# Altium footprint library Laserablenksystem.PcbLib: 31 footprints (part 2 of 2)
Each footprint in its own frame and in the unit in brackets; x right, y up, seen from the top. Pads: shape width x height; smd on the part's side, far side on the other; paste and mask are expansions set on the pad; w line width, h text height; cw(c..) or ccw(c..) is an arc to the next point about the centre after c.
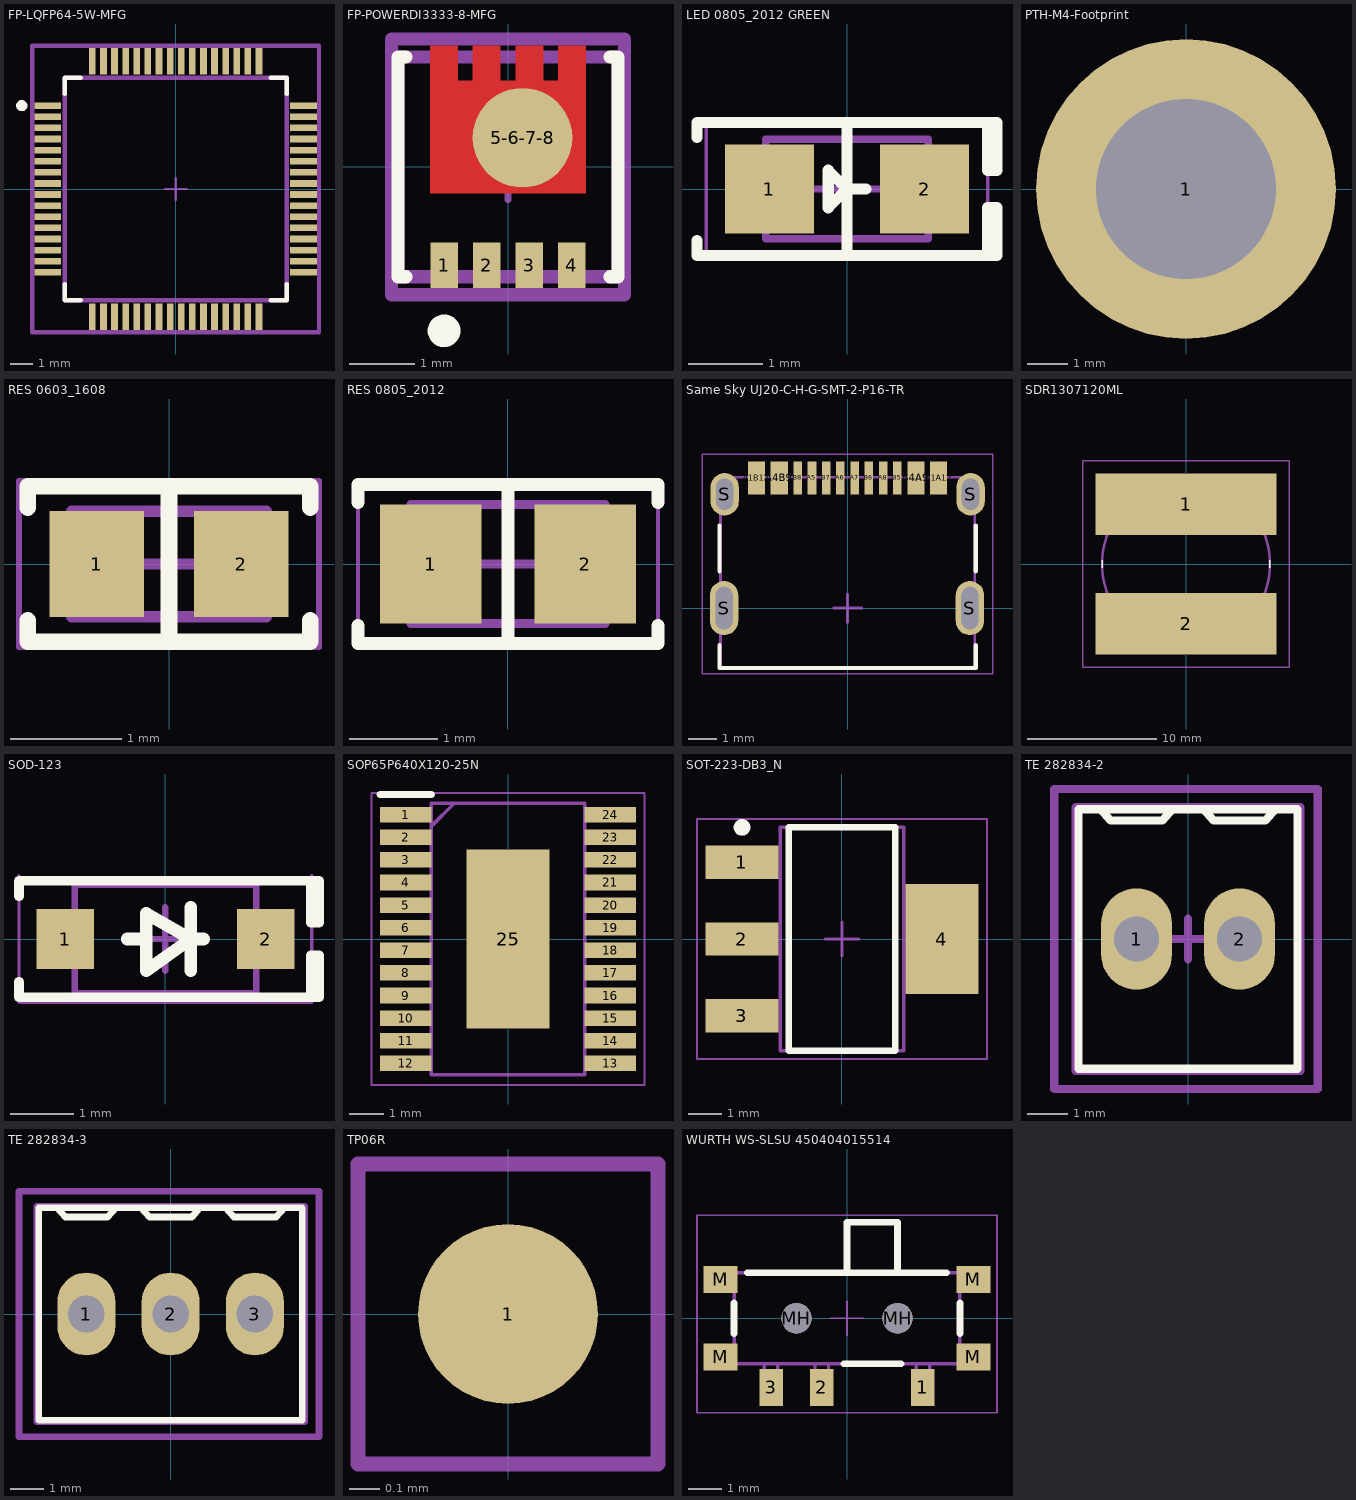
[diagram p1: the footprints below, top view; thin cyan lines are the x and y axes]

## FP-LQFP64-5W-MFG [mm]
pads (64):
  rect 1.2x0.3 smd paste+0 mask+0: 1(-5.75,3.75) 2(-5.75,3.25) 3(-5.75,2.75) 4(-5.75,2.25) 5(-5.75,1.75) 6(-5.75,1.25) 7(-5.75,0.75) 8(-5.75,0.25) 9(-5.75,-0.25) 10(-5.75,-0.75) 11(-5.75,-1.25) 12(-5.75,-1.75) 13(-5.75,-2.25) 14(-5.75,-2.75) 15(-5.75,-3.25) 16(-5.75,-3.75) 33(5.75,-3.75) 34(5.75,-3.25) 35(5.75,-2.75) 36(5.75,-2.25) 37(5.75,-1.75) 38(5.75,-1.25) 39(5.75,-0.75) 40(5.75,-0.25) 41(5.75,0.25) 42(5.75,0.75) 43(5.75,1.25) 44(5.75,1.75) 45(5.75,2.25) 46(5.75,2.75) 47(5.75,3.25) 48(5.75,3.75)
  rect 0.3x1.2 smd paste+0 mask+0: 17(-3.75,-5.75) 18(-3.25,-5.75) 19(-2.75,-5.75) 20(-2.25,-5.75) 21(-1.75,-5.75) 22(-1.25,-5.75) 23(-0.75,-5.75) 24(-0.25,-5.75) 25(0.25,-5.75) 26(0.75,-5.75) 27(1.25,-5.75) 28(1.75,-5.75) 29(2.25,-5.75) 30(2.75,-5.75) 31(3.25,-5.75) 32(3.75,-5.75) 49(3.75,5.75) 50(3.25,5.75) 51(2.75,5.75) 52(2.25,5.75) 53(1.75,5.75) 54(1.25,5.75) 55(0.75,5.75) 56(0.25,5.75) 57(-0.25,5.75) 58(-0.75,5.75) 59(-1.25,5.75) 60(-1.75,5.75) 61(-2.25,5.75) 62(-2.75,5.75) 63(-3.25,5.75) 64(-3.75,5.75)
Top Overlay:
  circle w0.25: c-6.925,3.75 r0.125
  lines w0.2: -5,-4.275 -5,-5 -4.275,-5 ; -5,4.275 -5,5 -4.275,5 ; 4.275,-5 5,-5 5,-4.275 ; 4.275,5 5,5 5,4.275
Top 3D Body:
  lines w0.2: -5,-5 5,-5 5,5 -5,5 -5,-5
Top Courtyard:
  lines w0.2: -6.45,-6.45 6.45,-6.45 6.45,6.45 -6.45,6.45 -6.45,-6.45
Top Assembly:
  lines w0.2: -6.45,-6.45 6.45,-6.45 6.45,6.45 -6.45,6.45 -6.45,-6.45
  text ".Designator" at 0,0.188 h1
Top Component Center:
  lines w0.1: -0.5,0 0.5,0 ; 0,-0.5 0,0.5
3D body "IC_STMicroelectronics_STM32L496RGT3_eec.STEP": height 0.25, standoff 0, extent -6.45,-6.45 6.45,6.45

## FP-POWERDI3333-8-MFG [mm]
pads (5):
  rect 0.42x0.7 smd paste+0 mask+0: 1(-0.975,-1.5) 2(-0.325,-1.5) 3(0.325,-1.5) 4(0.975,-1.5)
  round 1.519 smd paste+0 mask+0: 5-6-7-8(0.221,0.444)
Top Layer:
  region: -1.185,1.85 -0.765,1.85 -0.765,1.31 -0.535,1.31 -0.535,1.85 -0.115,1.85 -0.115,1.31 0.115,1.31 0.115,1.85 0.535,1.85 0.535,1.31 0.765,1.31 0.765,1.85 1.185,1.85 1.185,-0.4 -1.185,-0.4
Top Overlay:
  circle w0.25: c-0.975,-2.5 r0.125
  lines w0.2: -1.56,-1.675 -1.675,-1.675 -1.675,1.675 -1.56,1.675 ; 1.56,-1.675 1.675,-1.675 1.675,1.675 1.56,1.675
Top 3D Body:
  lines w0.2: -1.675,-1.675 -1.675,1.675 1.675,1.675 1.675,-1.675 -1.675,-1.675
Top Courtyard:
  lines w0.2: -1.775,-1.95 -1.775,1.95 1.775,1.95 1.775,-1.95 -1.775,-1.95
Top Assembly:
  lines w0.2: -1.775,-1.95 -1.775,1.95 1.775,1.95 1.775,-1.95 -1.775,-1.95
  text ".Designator" at 0,-0.001 h1
Top Component Center:
  lines w0.1: -0.5,0 0.5,0 ; 0,-0.5 0,0.5
3D body "Trans_Diodes_DMT6007LFGQ-13_eec.STEP": height 0.25, standoff 0, extent -1.775,-1.95 1.775,1.95

## LED 0805_2012 GREEN [mm] "Chip Diode, 2-Leads, Body 2.00x1.25mm, IPC Medium Density"
height 0.7
pads (2):
  rect 1.2x1.2 smd: 1(-1.05,0) 2(1.05,0)
Top Overlay:
  lines w0.15: -2.032,-0.7 -2.032,-0.9 1.905,-0.9 ; -2.032,0.7 -2.032,0.9 1.905,0.9 ; 0,-0.9 0,0.9 ; 0.254,0 0,0 ; 0,0 -0.254,-0.254 -0.254,0.254 0,0 ; 1.905,-0.9 2.032,-0.9 2.032,-0.254 1.905,-0.254 1.905,-0.9 ; 1.905,0.9 2.032,0.9 2.032,0.254 1.905,0.254 1.905,0.9
Mechanical 13:
  lines w0.1: -1.1,-0.675 -1.1,0.675 1.1,0.675 1.1,-0.675 -1.1,-0.675
Mechanical 15:
  lines w0.05: -1.905,-0.95 -1.905,0.95 1.905,0.95 1.905,-0.95 -1.905,-0.95
  lines w0.1: -0.5,0 0.5,0 ; 0,-0.5 0,0.5
3D body "LED 0805 Lens GREEN.STEP": height 0.9, standoff 0.3, extent -0.65,-0.625 0.65,0.625
3D body "LED 0805 Base GREEN.STEP": height 0.4, standoff 0, extent -1,-0.625 1,0.625

## PTH-M4-Footprint [mm]
pads (1):
  round 7.5 hole 4.5: 1(0,0)

## RES 0603_1608 [mm] "Chip Resistor, 2-Leads, Body 1.60x0.80mm, IPC Medium Density"
height 0.45
pads (2):
  rect 0.85x0.95 smd: 1(-0.65,0) 2(0.65,0)
Top Overlay:
  lines w0.15: -1.27,-0.508 -1.27,-0.7 1.27,-0.7 1.27,-0.508 ; -1.27,0.508 -1.27,0.7 1.27,0.7 1.27,0.508 ; 0,-0.7 0,0.7
Mechanical 13:
  lines w0.1: -0.875,-0.475 -0.875,0.475 0.875,0.475 0.875,-0.475 -0.875,-0.475
Mechanical 15:
  lines w0.05: -1.35,-0.75 -1.35,0.75 1.35,0.75 1.35,-0.75 -1.35,-0.75
  lines w0.1: -0.475,0 0.475,0 ; 0,-0.475 0,0.475
3D body "0603 resistor.STEP": height 0.45, standoff 0, extent -0.8,-0.4 0.8,0.4

## RES 0805_2012 [mm] "Chip Resistor, 2-Leads, Body 2.00x1.25mm, IPC Medium Density"
height 0.7
pads (2):
  rect 1.15x1.35 smd: 1(-0.875,0) 2(0.875,0)
Top Overlay:
  lines w0.15: -1.7,-0.7 -1.7,-0.9 1.7,-0.9 1.7,-0.7 ; -1.7,0.7 -1.7,0.9 1.7,0.9 1.7,0.7 ; 0,-0.9 0,0.9
Mechanical 13:
  lines w0.1: -1.1,-0.675 -1.1,0.675 1.1,0.675 1.1,-0.675 -1.1,-0.675
Mechanical 15:
  lines w0.05: -1.7,-0.95 -1.7,0.95 1.7,0.95 1.7,-0.95 -1.7,-0.95
  lines w0.1: -0.5,0 0.5,0 ; 0,-0.5 0,0.5
3D body "0805 resistor.STEP": height 0.6, standoff 0, extent -1,-0.625 1,0.625

## Same Sky UJ20-C-H-G-SMT-2-P16-TR [mm] "Type C, USB 2.0, 480 Mbps, 48 Vdc, 5 A, Horizontal, Surface Mount Anchor Pins Mounting Style, Surface Mount Contact Pin Type, Gold Plated 3 µin, 16 Pins, USB Receptacle"
height 3.16
pads (16):
  rect 0.6x1.15 smd: A1B12(-3.2,4.575) A4B9(-2.4,4.575) B1A12(3.2,4.575) B4A9(2.4,4.575)
  rect 0.3x1.15 smd: A5(-1.25,4.575) A6(-0.25,4.575) A7(0.25,4.575) A8(1.25,4.575) B5(1.75,4.575) B6(0.75,4.575) B7(-0.75,4.575) B8(-1.75,4.575)
  oval 1x1.9 hole 0.6 slot 1.5 at 90 deg: S(-4.34,0) S(4.3,0)
  oval 1x1.5 hole 0.6 slot 1.1 at 90 deg: S(-4.32,4) S(4.32,4)
Top Overlay:
  lines w0.15: -4.5,-1.3 -4.5,-2.1 4.5,-2.1 4.5,-1.3 ; -4.5,1.3 -4.5,2.9 ; 4.5,1.3 4.5,2.9
Mechanical 13:
  lines w0.1: -4.47,-2.1 -4.47,4.6 4.47,4.6 4.47,-2.1 -4.47,-2.1
Mechanical 15:
  lines w0.05: -5.1,-2.3 -5.1,5.4 5.1,5.4 5.1,-2.3 -5.1,-2.3
  lines w0.1: -0.5,0 0,0 ; 0,-0.5 0,0 ; 0,0.5 0,0 ; 0.5,0 0,0
3D body "Same Sky UJ20-C-H-G-SMT-2-P16-TR.step": height 3.26, standoff -0.51, extent -4.47,-2.1 4.47,4.65

## SDR1307120ML [mm]
pads (2):
  rect 14x4.75 smd: 1(0,4.625) 2(0,-4.625)
Top Overlay:
  lines w0.1: -6.5,-0.3 -6.5,0.3 ; 6.5,-0.3 6.5,0.3
Mechanical 13:
  lines w0.2: -6.5,0 ccw(c0,0) 6.5,0 ccw(c0,0) -6.5,0
Mechanical 15:
  lines w0.1: -8,-8 -8,8 8,8 8,-8 -8,-8
3D body "SDR1307-120ML.stp": height 7, standoff 0, extent -6.5,-6.5 6.5,6.5

## SOD-123 [mm] "SOD, 2-Leads, Body 1.55x3.70mm, IPC Medium Density"
height 1.35
pads (2):
  rect 0.9x0.95 smd: 1(-1.575,0) 2(1.575,0)
Top Overlay:
  lines w0.15: -2.3,-0.675 -2.3,-0.916 2.286,-0.916 ; -2.3,0.675 -2.3,0.916 2.286,0.916 ; 2.286,-0.916 2.286,-0.254 2.413,-0.254 2.413,-0.916 2.286,-0.916 ; 2.286,0.916 2.413,0.916 2.413,0.254 2.286,0.254 2.286,0.916
  lines w0.2: -0.6,0 -0.3,0 ; 0.4,-0.5 0.4,0.5 ; 0.6,0 0.4,0 ; 0.4,0 -0.3,-0.5 -0.3,0.4 0.4,0
Mechanical 13:
  lines w0.1: -1.425,-0.85 1.425,-0.85 1.425,0.85 -1.425,0.85 -1.425,-0.85
Mechanical 15:
  lines w0.05: -2.3,0.9 2.3,0.9 ; -2.3,1 -2.3,-1 2.3,-1 2.3,1
  lines w0.1: -0.5,0 0.5,0 ; 0,-0.5 0,0.5
3D body "SOD-123.STEP": height 1.35, standoff 0, extent -1.864,-0.775 1.864,0.775

## SOP65P640X120-25N [mm]
pads (25):
  rect 1.475x0.45 smd: 1(-2.938,3.575) 2(-2.938,2.925) 3(-2.938,2.275) 4(-2.938,1.625) 5(-2.938,0.975) 6(-2.938,0.325) 7(-2.938,-0.325) 8(-2.938,-0.975) 9(-2.938,-1.625) 10(-2.938,-2.275) 11(-2.938,-2.925) 12(-2.938,-3.575) 13(2.938,-3.575) 14(2.938,-2.925) 15(2.938,-2.275) 16(2.938,-1.625) 17(2.938,-0.975) 18(2.938,-0.325) 19(2.938,0.325) 20(2.938,0.975) 21(2.938,1.625) 22(2.938,2.275) 23(2.938,2.925) 24(2.938,3.575)
  rect 2.4x5.16 smd: 25(0,0)
Top Overlay:
  lines w0.2: -3.675,4.15 -2.2,4.15
Mechanical 13:
  lines w0.1: -2.2,3.25 -1.55,3.9 ; -2.2,-3.9 -2.2,3.9 2.2,3.9 2.2,-3.9 -2.2,-3.9
Mechanical 15:
  lines w0.05: -3.925,-4.2 -3.925,4.2 3.925,4.2 3.925,-4.2 -3.925,-4.2
3D body "DRV10975ZPWPR.stp": height 1, standoff 0, extent -3.21,-3.9 3.21,3.9

## SOT-223-DB3_N [mm] "SOT223, 4-Leads, Body 6.5x3.5mm, Pitch 2.3mm, Lead Span 7mm, IPC Medium Density"
height 1.8
pads (4):
  rect 2.2x1 smd: 1(-3,2.3) 2(-3,0) 3(-3,-2.3)
  rect 2.2x3.3 smd: 4(3,0)
Top Overlay:
  circle w0.25: c-3,3.35 r0.125
  lines w0.2: -1.6,-3.35 1.6,-3.35 1.6,3.35 -1.6,3.35 -1.6,-3.35
Mechanical 13:
  lines w0.1: -1.85,-3.35 1.85,-3.35 1.85,3.35 -1.85,3.35 -1.85,-3.35
Mechanical 15:
  lines w0.05: -4.35,-3.6 4.35,-3.6 4.35,3.6 -4.35,3.6 -4.35,-3.6
  lines w0.1: -0.5,0 0.5,0 ; 0,-0.5 0,0.5
3D body: height 1.8, standoff 0.02, extent -1.85,-3.35 1.85,3.35

## TE 282834-2 [mm]
height 10
pads (2):
  oval 1.75x2.5 hole 1.1: 1(-1.27,0) 2(1.27,0)
Top Overlay:
  lines w0.2: -2.159,3.2 -1.905,2.921 -0.635,2.921 -0.381,3.2 ; 0.381,3.2 0.635,2.921 1.905,2.921 2.159,3.2 ; -2.7,-3.2 -2.6,-3.2 2.7,-3.2 2.7,3.2 -2.7,3.2 -2.7,-3.2
Mechanical 13:
  lines w0.2: -2.77,-3.25 -2.77,3.25 2.77,3.25 2.77,-3.25 -2.77,-3.25
Mechanical 15:
  lines w0.2: -0.5,0 0.5,0 ; 0,-0.5 0,0.5 ; -3.3,-3.7 3.2,-3.7 3.2,-2.9 3.2,3.7 -3.3,3.7 -3.3,-3.3 -3.3,-3.7
3D body "TE Term Block 2port 282834-2-c-3d.STEP": height 10, standoff -3.4, extent -2.77,-3.25 2.77,3.25

## TE 282834-3 [mm]
height 10
pads (3):
  oval 1.75x2.5 hole 1.1: 1(-2.54,0) 2(0,0) 3(2.54,0)
Top Overlay:
  lines w0.2: -3.429,3.2 -3.175,2.921 -1.905,2.921 -1.651,3.2 ; -0.889,3.2 -0.635,2.921 0.635,2.921 0.889,3.2 ; 1.651,3.2 1.905,2.921 3.175,2.921 3.429,3.2 ; -3.97,-3.2 -3.87,-3.2 3.97,-3.2 3.97,3.2 -3.97,3.2 -3.97,-3.2
Mechanical 13:
  lines w0.2: -4.04,-3.25 -4.04,3.25 4.04,3.25 4.04,-3.25 -4.04,-3.25
Mechanical 15:
  lines w0.2: -0.5,0 0.5,0 ; 0,-0.5 0,0.5 ; -4.57,-3.7 4.47,-3.7 4.47,-2.9 4.47,3.7 -4.57,3.7 -4.57,-3.3 -4.57,-3.7
3D body "TE Term Block 3port 282834-3-c-3d.STEP": height 10, standoff -3.4, extent -4.04,-3.25 4.04,3.25

## TP06R [mm] "Testpoint, round, d=0.6mm"
pads (1):
  round 0.6 smd paste-1: 1(0,0)
Top Assembly:
  lines w0.05: -0.5,-0.5 0.5,-0.5 0.5,0.5 -0.5,0.5 -0.5,-0.5
Top Designator:
  text ".Designator" at -1.27,0.254 h0.6

## WURTH WS-SLSU 450404015514 [mm] "Right angle Slide Switch"
height 1.4
pads (9):
  rect 0.7x1.1 smd: 1(2.25,-2.05) 2(-0.75,-2.05) 3(-2.25,-2.05)
  rect 1x0.8 smd: M(-3.75,-1.15) M(-3.75,1.15) M(3.75,-1.15) M(3.75,1.15)
  round 0.9 hole 0.9 unplated: MH(-1.5,0) MH(1.5,0)
Top Overlay:
  lines w0.2: -3.35,-0.45 -3.35,0.45 ; -2.95,1.35 2.95,1.35 ; -0.1,-1.35 1.6,-1.35 ; 0,1.35 0,2.85 1.5,2.85 1.5,1.35 ; 3.35,-0.45 3.35,0.45
Top Courtyard:
  lines w0.05: -0.5,0 0.5,0 ; 0,-0.5 0,0.5 ; -4.45,-2.8 4.45,-2.8 4.45,3.05 -4.45,3.05 -4.45,-2.8
Top Component Outline:
  lines w0.1: -3.35,-1.25 -3.85,-1.25 -3.85,-0.85 -3.35,-0.85 ; -3.35,0.85 -3.85,0.85 -3.85,1.25 -3.35,1.25 ; -2.45,-1.35 -2.45,-2.25 -2.05,-2.25 -2.05,-1.35 ; -0.95,-1.35 -0.95,-2.25 -0.55,-2.25 -0.55,-1.35 ; 0,1.35 0,2.85 1.5,2.85 1.5,1.35 ; 2.05,-1.35 2.05,-2.25 2.45,-2.25 2.45,-1.35 ; 3.35,-1.25 3.85,-1.25 3.85,-0.85 3.35,-0.85 ; 3.35,0.85 3.85,0.85 3.85,1.25 3.35,1.25 ; -3.35,-1.35 -3.35,1.35 3.35,1.35 3.35,-1.35 -3.35,-1.35
3D body "450404015514.stp": height 1.4, standoff -0.5, extent -3.85,-2.25 3.85,2.88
